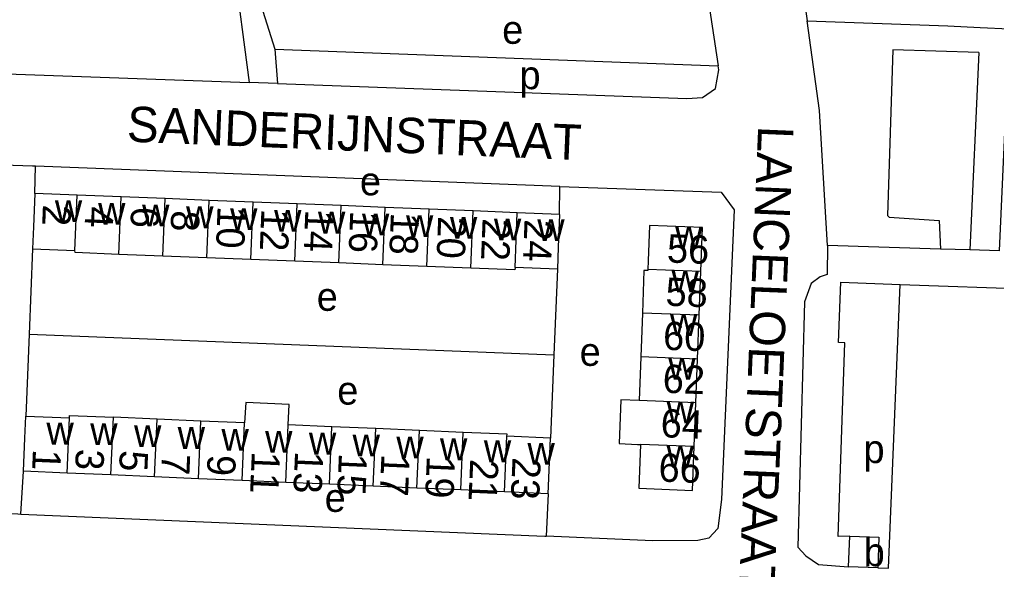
# Model space of a CAD drawing. Extents: x 159675 to 162108, y 386471 to 388472.
# Drawn here: x 160707.8 to 160845.9, y 386610.4 to 386688.1 of the extents above; entities that cross this region are included whole.
import ezdxf

# ---------------------------------------------------------------- set-up
doc = ezdxf.new("R2010")
doc.units = 0
for name, color, linetype in [('BLT_Basislijn', 7, 'Continuous'), ('BLT_Bebouwing', 7, 'Continuous'), ('BLT_Centroide', 7, 'Continuous'), ('BLT_Huisnummer', 7, 'Continuous'), ('BLT_Huisnummer_ tussenligend', 7, 'Continuous'), ('BLT_Onderverdeling_panden', 7, 'Continuous'), ('BLT_Straatnaam', 7, 'Continuous')]:
    doc.layers.add(name, color=color, linetype=linetype)

msp = doc.modelspace()

# ---------------------------------------------------------------- linework, layer by layer
at = {"layer": 'BLT_Basislijn'}
for p, q in [((160803.26, 386703.26), (160806.56, 386681.53)), ((160818.43, 386692.57), (160819.13, 386687.91)), ((160741.61, 386691.09), (160743.85, 386683.89)), ((160819.13, 386687.91), (160839.02, 386687.17)), ((160839.02, 386687.17), (160843.55, 386686.94)), ((160743.85, 386683.89), (160744.25, 386679.02)), ((160743.85, 386683.89), (160806.56, 386681.53)), ((160843.38, 386683.41), (160842.1, 386655.53)), ((160700, 386680.64), (160740.25, 386679.17)), ((160744.25, 386679.02), (160740.25, 386679.17)), ((160709.94, 386663.51), (160710.05, 386667.36)), ((160784.18, 386664.48), (160710.05, 386667.36)), ((160784.13, 386660.55), (160784.18, 386664.48)), ((160837.95, 386655.64), (160821.97, 386656.17)), ((160709.62, 386655.68), (160709.14, 386643.63)), ((160842.1, 386655.53), (160837.95, 386655.64)), ((160783.82, 386652.81), (160783.32, 386640.68)), ((160830.61, 386610.54), (160832.28, 386650.66)), ((160709.14, 386643.63), (160708.67, 386632.05)), ((160709.14, 386643.63), (160783.32, 386640.68)), ((160824.44, 386642.41), (160823.54, 386642.45)), ((160783.32, 386640.68), (160782.83, 386628.94)), ((160707.96, 386618.21), (160708.34, 386624.26)), ((160782.49, 386621.08), (160782.21, 386615.08)), ((160829.1, 386610.61), (160830.61, 386610.54))]:
    msp.add_line(p, q, dxfattribs=at)
for points in [[(160832.28, 386650.66), (160851.25, 386650), (160851.9, 386677.8), (160856.69, 386677.62), (160858.83, 386709.86), (160871.23, 386709.36)], [(160700, 386701.07), (160736.74, 386699.67), (160737.6, 386698.3), (160738.01, 386696.01), (160740.25, 386679.17)], [(160821.97, 386656.17), (160820.86, 386675.24), (160819.13, 386687.91)], [(160843.55, 386686.94), (160847.66, 386686.77), (160846.26, 386655.4), (160842.1, 386655.53)], [(160843.38, 386683.41), (160831.23, 386683.81), (160830.49, 386660.37), (160830.72, 386660.15), (160837.76, 386659.7), (160837.95, 386655.64)], [(160744.25, 386679.02), (160802.1, 386676.93), (160804.33, 386677.06), (160806.16, 386678.33), (160806.65, 386680.96), (160806.56, 386681.53)], [(160710.05, 386667.36), (160709.6, 386667.38), (160700, 386667.7)], [(160784.18, 386664.48), (160806.94, 386663.68), (160808.78, 386661.2), (160807, 386620.28), (160806.48, 386616.14), (160805.21, 386614.8), (160803.68, 386614.45), (160797.29, 386614.44), (160782.21, 386615.08)], [(160821.97, 386656.17), (160821.96, 386652.03), (160820.97, 386651.74), (160819.7, 386650.79), (160818.74, 386648.17), (160817.82, 386613.51), (160818.95, 386612.28), (160820.72, 386611.09), (160824.97, 386610.77)], [(160823.54, 386642.45), (160823.9, 386650.95), (160832.28, 386650.66)], [(160825.13, 386615.08), (160823.5, 386615.01), (160824.44, 386642.41)], [(160700, 386618.57), (160707.54, 386618.23), (160707.96, 386618.21)], [(160707.96, 386618.21), (160782.02, 386615.09), (160782.21, 386615.08)]]:
    msp.add_lwpolyline(points, dxfattribs=at)
at = {"layer": 'BLT_Bebouwing'}
for p, q in [((160715.93, 386663.27), (160709.94, 386663.51)), ((160722.17, 386663.03), (160715.93, 386663.27)), ((160728.38, 386662.78), (160722.17, 386663.03)), ((160734.6, 386662.53), (160728.38, 386662.78)), ((160740.81, 386662.28), (160734.6, 386662.53)), ((160747.03, 386662.03), (160740.81, 386662.28)), ((160753.24, 386661.79), (160747.03, 386662.03)), ((160759.46, 386661.54), (160753.24, 386661.79)), ((160765.68, 386661.29), (160759.46, 386661.54)), ((160771.89, 386661.04), (160765.68, 386661.29)), ((160778.13, 386660.79), (160771.89, 386661.04)), ((160784.13, 386660.55), (160778.13, 386660.79)), ((160709.62, 386655.68), (160715.62, 386655.44)), ((160728.06, 386654.66), (160721.84, 386654.9)), ((160734.28, 386654.41), (160728.06, 386654.66)), ((160740.49, 386654.17), (160734.28, 386654.41)), ((160746.71, 386653.92), (160740.49, 386654.17)), ((160752.92, 386653.68), (160746.71, 386653.92)), ((160759.14, 386653.43), (160752.92, 386653.68)), ((160765.36, 386653.18), (160759.14, 386653.43)), ((160771.57, 386652.94), (160765.36, 386653.18)), ((160783.82, 386652.81), (160777.83, 386653.05)), ((160803.87, 386646.3), (160804.1, 386652.49)), ((160795.82, 386646.61), (160795.59, 386640.42)), ((160803.63, 386640.11), (160803.87, 386646.3)), ((160795.59, 386640.42), (160795.35, 386634.23)), ((160803.4, 386633.93), (160803.63, 386640.11)), ((160803.16, 386627.74), (160803.4, 386633.93)), ((160708.67, 386632.05), (160714.85, 386631.79)), ((160727.23, 386631.61), (160721.05, 386631.88)), ((160733.41, 386631.34), (160727.23, 386631.61)), ((160739.59, 386631.08), (160733.41, 386631.34)), ((160751.95, 386630.54), (160745.77, 386630.81)), ((160758.13, 386630.27), (160751.95, 386630.54)), ((160764.31, 386630), (160758.13, 386630.27)), ((160770.49, 386629.73), (160764.31, 386630)), ((160782.83, 386628.94), (160776.66, 386629.21)), ((160782.49, 386621.08), (160782.83, 386628.94)), ((160795.12, 386628.05), (160795.58, 386628.03)), ((160714.52, 386624), (160708.34, 386624.26)), ((160720.7, 386623.73), (160714.52, 386624)), ((160726.88, 386623.47), (160720.7, 386623.73)), ((160733.06, 386623.2), (160726.88, 386623.47)), ((160739.24, 386622.94), (160733.06, 386623.2)), ((160745.42, 386622.67), (160739.24, 386622.94)), ((160751.6, 386622.41), (160745.42, 386622.67)), ((160757.78, 386622.14), (160751.6, 386622.41)), ((160763.96, 386621.88), (160757.78, 386622.14)), ((160770.14, 386621.61), (160763.96, 386621.88)), ((160776.32, 386621.35), (160770.14, 386621.61)), ((160782.49, 386621.08), (160776.32, 386621.35)), ((160824.97, 386610.77), (160825.13, 386615.08)), ((160829.1, 386610.61), (160824.97, 386610.77))]:
    msp.add_line(p, q, dxfattribs=at)
for points in [[(160709.94, 386663.51), (160709.75, 386658.8), (160709.62, 386655.68)], [(160784.13, 386660.55), (160783.94, 386655.93), (160783.82, 386652.81)], [(160804.1, 386652.49), (160804.34, 386658.68), (160796.82, 386658.96), (160796.63, 386653.97), (160796.59, 386652.78)], [(160721.84, 386654.9), (160715.63, 386655.15), (160715.62, 386655.44)], [(160777.83, 386653.05), (160777.78, 386652.7), (160771.57, 386652.94)], [(160796.59, 386652.78), (160796.58, 386652.62), (160796.05, 386652.64), (160795.82, 386646.61)], [(160795.35, 386634.23), (160792.78, 386634.33), (160792.54, 386628.19), (160795.12, 386628.05)], [(160745.77, 386630.81), (160745.88, 386633.68), (160739.75, 386633.95), (160739.59, 386631.08)], [(160708.34, 386624.26), (160708.54, 386628.93), (160708.67, 386632.05)], [(160714.85, 386631.79), (160714.84, 386632.15), (160721.05, 386631.88)], [(160776.66, 386629.21), (160776.69, 386629.47), (160770.49, 386629.73)], [(160795.58, 386628.03), (160795.34, 386621.84), (160802.93, 386621.55), (160803.16, 386627.74)], [(160825.13, 386615.08), (160829.26, 386614.92), (160829.1, 386610.61)]]:
    msp.add_lwpolyline(points, dxfattribs=at)
at = {"layer": 'BLT_Onderverdeling_panden'}
for p, q in [((160715.62, 386655.44), (160715.93, 386663.27)), ((160721.84, 386654.9), (160722.17, 386663.03)), ((160728.06, 386654.66), (160728.38, 386662.78)), ((160734.28, 386654.41), (160734.6, 386662.53)), ((160740.49, 386654.17), (160740.81, 386662.28)), ((160746.71, 386653.92), (160747.03, 386662.03)), ((160752.92, 386653.68), (160753.24, 386661.79)), ((160759.14, 386653.43), (160759.46, 386661.54)), ((160765.36, 386653.18), (160765.68, 386661.29)), ((160771.57, 386652.94), (160771.89, 386661.04)), ((160777.83, 386653.05), (160778.13, 386660.79)), ((160804.1, 386652.49), (160796.59, 386652.78)), ((160803.87, 386646.3), (160795.82, 386646.61)), ((160803.63, 386640.11), (160795.59, 386640.42)), ((160803.4, 386633.93), (160795.35, 386634.23)), ((160714.52, 386624), (160714.85, 386631.79)), ((160720.7, 386623.73), (160721.05, 386631.88)), ((160726.88, 386623.47), (160727.23, 386631.61)), ((160733.06, 386623.2), (160733.41, 386631.34)), ((160739.24, 386622.94), (160739.59, 386631.08)), ((160745.42, 386622.67), (160745.77, 386630.81)), ((160751.6, 386622.41), (160751.95, 386630.54)), ((160757.78, 386622.14), (160758.13, 386630.27)), ((160763.96, 386621.88), (160764.31, 386630)), ((160770.14, 386621.61), (160770.49, 386629.73)), ((160776.32, 386621.35), (160776.66, 386629.21)), ((160803.16, 386627.74), (160795.58, 386628.03))]:
    msp.add_line(p, q, dxfattribs=at)

# ---------------------------------------------------------------- texts
at = {"layer": 'BLT_Centroide'}
for s, p in [('e', (160776.01, 386684.65)), ('p', (160778.46, 386678.24)), ('e', (160755.9, 386663.24)), ('w', (160712.78, 386659.48)), ('w', (160718.89, 386659.09)), ('w', (160725.11, 386658.84)), ('w', (160731.33, 386658.59)), ('w', (160737.55, 386658.34)), ('w', (160743.77, 386658.09)), ('w', (160749.97, 386657.84)), ('w', (160756.19, 386657.59)), ('w', (160762.41, 386657.36)), ('w', (160768.62, 386657.12)), ('w', (160774.84, 386656.88)), ('w', (160780.97, 386656.8)), ('w', (160800.47, 386655.72)), ('w', (160799.96, 386649.53)), ('e', (160749.8, 386646.92)), ('w', (160799.73, 386643.38)), ('e', (160786.96, 386639.14)), ('w', (160799.49, 386637.19)), ('e', (160752.7, 386633.67)), ('w', (160799.26, 386631)), ('w', (160711.59, 386628.03)), ('w', (160717.78, 386627.94)), ('w', (160723.97, 386627.67)), ('w', (160730.14, 386627.42)), ('w', (160736.33, 386627.14)), ('w', (160742.5, 386626.88)), ('w', (160748.69, 386626.61)), ('w', (160754.86, 386626.34)), ('w', (160761.05, 386626.08)), ('w', (160767.22, 386625.81)), ('w', (160773.42, 386625.53)), ('p', (160827.08, 386625.41)), ('w', (160779.58, 386625.16)), ('w', (160799.25, 386624.78)), ('e', (160750.92, 386618.51)), ('b', (160827.11, 386610.84))]:
    msp.add_text(s, height=4, dxfattribs=at).set_placement(p)
at = {"layer": 'BLT_Huisnummer'}
for s, rotation, p in [('2', 267.7291, (160711.1, 386661.96)), ('6', 267.7291, (160723.57, 386661.68)), ('10', 267.7291, (160735.79, 386661.75)), ('14', 267.7291, (160748.19, 386661.24)), ('18', 267.7291, (160760.29, 386660.85)), ('24', 267.7291, (160779.18, 386659.9)), ('56', 357.8138, (160799.25, 386653.76)), ('60', 357.8138, (160798.7, 386641.43)), ('1', 267.5563, (160709.69, 386627.41)), ('5', 267.5563, (160721.98, 386627.28)), ('9', 267.5563, (160734.38, 386626.64)), ('13', 267.5563, (160746.74, 386627.13)), ('17', 267.5563, (160758.95, 386626.74)), ('23', 267.5563, (160777.48, 386626.27)), ('66', 357.8138, (160798.06, 386622.81))]:
    msp.add_text(s, height=4, rotation=rotation, dxfattribs=at).set_placement(p)
at = {"layer": 'BLT_Huisnummer_ tussenligend'}
for s, rotation, p in [('4', 267.7348, (160717.1, 386661.72)), ('8', 267.7348, (160729.25, 386661.17)), ('12', 267.7348, (160741.98, 386661.37)), ('16', 267.7348, (160754.54, 386661.11)), ('20', 267.7348, (160766.97, 386660.31)), ('22', 267.7348, (160773.25, 386660.02)), ('58', 357.8154, (160799.05, 386647.65)), ('62', 357.8154, (160798.65, 386635.36)), ('64', 357.8154, (160798.36, 386629.07)), ('3', 267.5455, (160715.77, 386627.46)), ('7', 267.5455, (160727.92, 386626.79)), ('11', 267.5455, (160740.63, 386627.09)), ('15', 267.5455, (160752.94, 386626.85)), ('19', 267.5455, (160765.37, 386626.45)), ('21', 267.5455, (160771.5, 386626.01))]:
    msp.add_text(s, height=4, rotation=rotation, dxfattribs=at).set_placement(p)
at = {"layer": 'BLT_Straatnaam'}
for s, rotation, p in [('SANDERIJNSTRAAT', 357.6531, (160722.91, 386670.84)), ('LANCELOETSTRAAT', 267.6271, (160812.2, 386673.11))]:
    msp.add_text(s, height=5, rotation=rotation, dxfattribs=at).set_placement(p)

doc.saveas('drawing.dxf')
